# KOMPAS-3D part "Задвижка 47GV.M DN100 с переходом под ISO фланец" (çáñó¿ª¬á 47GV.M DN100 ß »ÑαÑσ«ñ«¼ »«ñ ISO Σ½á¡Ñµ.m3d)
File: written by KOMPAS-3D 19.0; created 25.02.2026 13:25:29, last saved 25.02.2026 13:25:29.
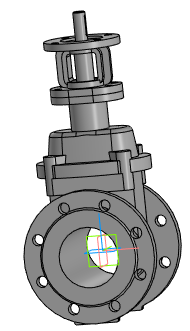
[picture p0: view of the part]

Document properties: Автор: Энергия; Полное имя файла: 47GV.M DN100\Задвижка 47GV.M DN100 с маховиком.a3d

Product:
- Part/product: Задвижка 47GV.M DN100 с переходом под ISO фланец
    Масса: 28.6026
  - Component: Задвижка с обрезиненным клином DN80. Сборочный чертеж  | designation DR.47GVM.080.16.00.00СБ  | pos. 0  | Масса: 15.8764; Раздел спецификации: Документация; Форматы листов документа: 2xA3; source file: 47GV.M DN100\DR.47GVM.080.16.00.000 СБ - Задвижка с обрезиненным клином DN80.cdw
- Part/product: Задвижка 47GV.M DN100 с переходом под ISO фланец  | designation 01
    Масса: 15.8677
  - Component [detail]: Крышка DN100  | pos. 4  | Материал: ВЧ50 ГОСТ 7293-85 (density 7200 kg/m3); Масса: 6.92658; Раздел спецификации: Детали; Форматы листов документа: 2xA3; source file: 47GV.M DN100\DR.47GVM.100.16.00.002 - Крышка.cdw, 47GV.M DN100\Крышка DN100.m3d
  - Component [detail]: Корпус DN100  | pos. 3  | Материал: ВЧ50 ГОСТ 7293-85 (density 7200 kg/m3); Масса: 19.2555; Раздел спецификации: Детали; Форматы листов документа: 2xA3; source file: 47GV.M DN100\DR.47GV.100.16.00.001 - Корпус.cdw, 47GV.M DN100\DR.47GVM.050.16.00.001 - Корпус.cdw, 47GV.M DN100\DR.47GVM.100.16.00.001 - Корпус.cdw, 47GV.M DN100\Корпус DN100.m3d
  - Component [assembly]: Клин с направляющими  | designation DR.47GVM.080.16.01.000  | pos. 4  | Раздел спецификации: Сборочные единицы; Форматы листов документа: A4; source file: 47GV.M DN100\DR.47GVM.080.16.01.000 - Клин с направляющими.a3d, 47GV.M DN100\DR.47GVM.080.16.01.000 - Клин с направляющими.spw, 47GV.M DN100\DR.47GVM.080.16.01.000 СБ - Клин с направляющими.cdw
  - Component [detail]: Шпиндель  | pos. 5  | Материал: Сталь 20Х13 ГОСТ 5632 - 2014 (density 7670 kg/m3); Масса: 0.114456; Раздел спецификации: Детали; Форматы листов документа: A3; source file: 47GV.M DN80\DR.47GVM.080.16.00.003 - Шпиндель.cdw, 47GV.M DN80\Шпиндель DN80.m3d
  - Component: Стойка  | Материал: ВЧ50 ГОСТ 7293-85 (density 7200 kg/m3); Масса: 1.9123; source file: 47GV.M DN80\DR.47GVAM.100.16.00.001 - Стойка.cdw, 47GV.M DN80\Стойка DN100.m3d
  - Component: Удлинитель шпинделя  | Материал: Сталь 20Х13 ГОСТ 5632-72 (density 7670 kg/m3); Масса: 0.393756; source file: 47GV.M DN80\DR.47GVAM.100.16.00.002 - Удлинитель шпинделя.cdw, 47GV.M DN80\Удлинитель шпинделя DN100.m3d

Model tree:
1. Операция без истории:1

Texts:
  Точка начала. Х
  Точка начала. Y
  Точка начала. Z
